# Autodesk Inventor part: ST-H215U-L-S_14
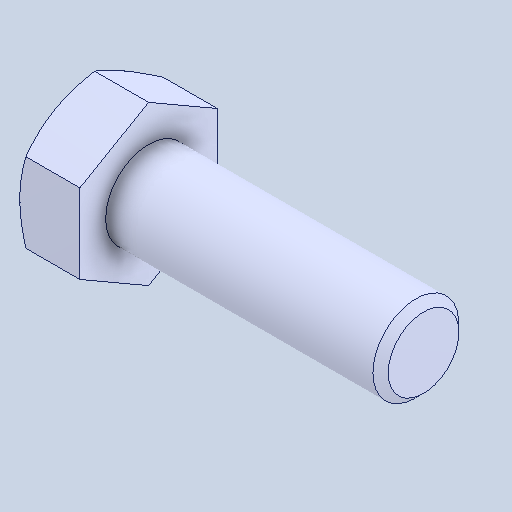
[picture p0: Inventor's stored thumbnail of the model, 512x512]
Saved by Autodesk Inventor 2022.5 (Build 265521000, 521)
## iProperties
Created: 2024-07
Part Number: ST-H215U-L-S_14
Material: 一般
Document SubType Name: Modeling
Designer: ImaoCorp
Density: 1 g/cm^3
Appearance: 既定
Author: ImaoCorp
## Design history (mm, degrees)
feature "ST-H215U-L-S_14"
node "ソリッド1"
